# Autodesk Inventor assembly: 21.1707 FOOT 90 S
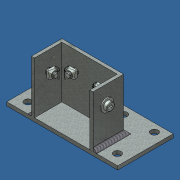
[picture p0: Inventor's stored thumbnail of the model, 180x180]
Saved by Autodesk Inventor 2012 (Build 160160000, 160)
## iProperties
Created: 2007-04
Part Number: 21.1707 FOOT 90 S
Document SubType Name: Weldment
Designer: Andy Moles
Weld Material: Welded Aluminum-6061
Author: Andy Moles
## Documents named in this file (5)
- C:\Andys Backup Data\ANDY'S INVENTOR\INVENTOR LIBRARIES\PARTS LIBRARY\FEET WHEELS FLOOR FASTENING SUPPORTS\21.1707 FOOT 90 S.iam
- C:\Andys Backup Data\ANDY'S INVENTOR\INVENTOR LIBRARIES\PARTS LIBRARY\FEET WHEELS FLOOR FASTENING SUPPORTS\SUBCOMPONENTS\21.1707 FOOT 90 S.ipt
- C:\Andys Backup Data\ANDY'S INVENTOR\INVENTOR LIBRARIES\PARTS LIBRARY\FASTENING ELEMENTS\SCREWS CAP\21.1202 M8X20.ipt
- C:\Andys Backup Data\ANDY'S INVENTOR\INVENTOR LIBRARIES\PARTS LIBRARY\FASTENING ELEMENTS\NUTS\21.1351_2 M8 SQUARE NUT POS FXG.ipt
- C:\Andys Backup Data\ANDY'S INVENTOR\INVENTOR LIBRARIES\PARTS LIBRARY\FASTENING ELEMENTS\WASHERS\21.1123 M8 ROUND O.D. 20mm.ipt
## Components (13 placed, 4 different names)
1. 21.1707 FOOT 90 S:1 — Mate:1, Flush:1, Flush:2, Insert:1, Insert:2, Insert:3, Insert:4, Insert:9, Insert:10, Insert:11, Insert:12
2. 21.1123 M8 ROUND O.D. 20mm:1 — Insert:1, Insert:5
3. 21.1123 M8 ROUND O.D. 20mm:2 — Insert:2, Insert:6
4. 21.1123 M8 ROUND O.D. 20mm:3 — Insert:3, Insert:7
5. 21.1123 M8 ROUND O.D. 20mm:4 — Insert:4, Insert:8
6. 21.1202  M8 x 20:1 — Insert:5
7. 21.1202  M8 x 20:2 — Insert:6
8. 21.1202  M8 x 20:3 — Insert:7
9. 21.1202  M8 x 20:4 — Insert:8
10. 21.1351_2 M8 SQUARE NUT POS FXG:1 — Insert:12
11. 21.1351_2 M8 SQUARE NUT POS FXG:2 — Insert:11
12. 21.1351_2 M8 SQUARE NUT POS FXG:3 — Insert:10
13. 21.1351_2 M8 SQUARE NUT POS FXG:4 — Insert:9
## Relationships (15: Insert 12, Flush 2, Mate 1)
- Mate:1: 21.1707 FOOT 90 S:1
- Flush:1: 21.1707 FOOT 90 S:1
- Flush:2: 21.1707 FOOT 90 S:1
- Insert:1: 21.1707 FOOT 90 S:1 ↔ 21.1123 M8 ROUND O.D. 20mm:1
- Insert:2: 21.1707 FOOT 90 S:1 ↔ 21.1123 M8 ROUND O.D. 20mm:2
- Insert:3: 21.1707 FOOT 90 S:1 ↔ 21.1123 M8 ROUND O.D. 20mm:3
- Insert:4: 21.1707 FOOT 90 S:1 ↔ 21.1123 M8 ROUND O.D. 20mm:4
- Insert:5: 21.1123 M8 ROUND O.D. 20mm:1 ↔ 21.1202  M8 x 20:1
- Insert:6: 21.1123 M8 ROUND O.D. 20mm:2 ↔ 21.1202  M8 x 20:2
- Insert:7: 21.1123 M8 ROUND O.D. 20mm:3 ↔ 21.1202  M8 x 20:3
- Insert:8: 21.1123 M8 ROUND O.D. 20mm:4 ↔ 21.1202  M8 x 20:4
- Insert:9: 21.1707 FOOT 90 S:1 ↔ 21.1351_2 M8 SQUARE NUT POS FXG:4
- Insert:10: 21.1707 FOOT 90 S:1 ↔ 21.1351_2 M8 SQUARE NUT POS FXG:3
- Insert:11: 21.1707 FOOT 90 S:1 ↔ 21.1351_2 M8 SQUARE NUT POS FXG:2
- Insert:12: 21.1707 FOOT 90 S:1 ↔ 21.1351_2 M8 SQUARE NUT POS FXG:1
